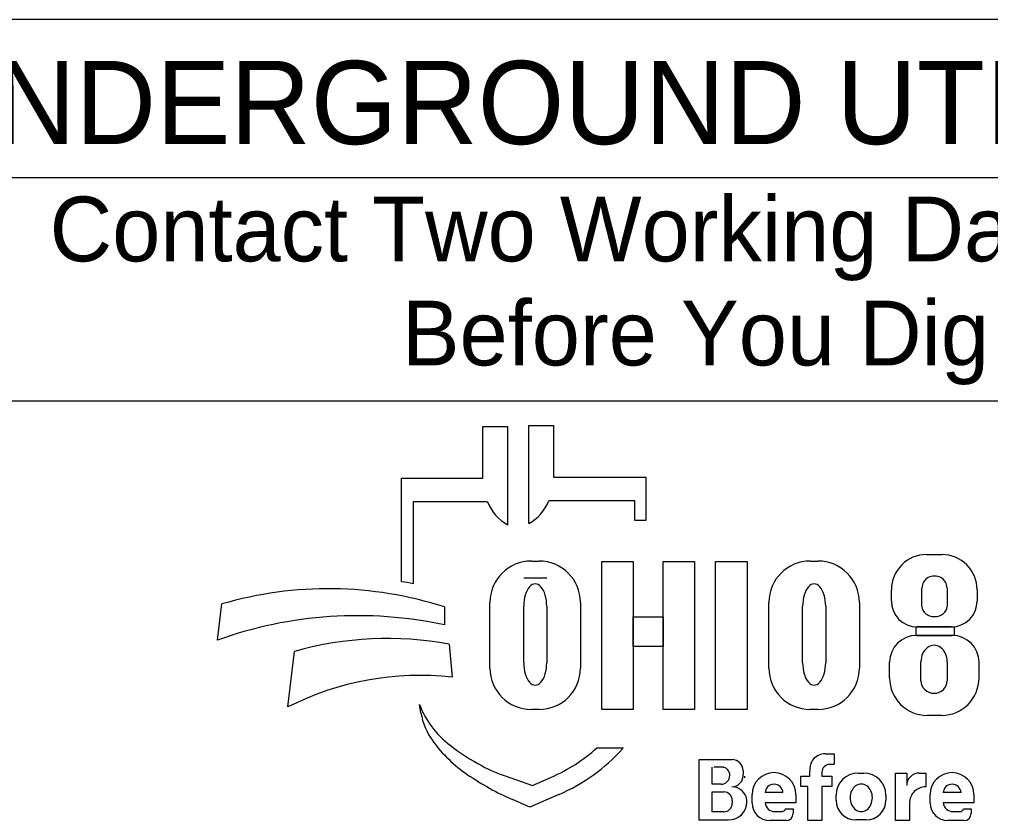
# Model space of a CAD drawing. Extents: x 0 to 43.4, y -8.1 to 22.
# Drawn here: x 13.492 to 15.591, y 1.457 to 3.19 of the extents above; entities that cross this region are included whole.
import ezdxf

# ---------------------------------------------------------------- set-up
doc = ezdxf.new("R2010")
doc.units = 0
doc.layers.add('SH_Data', color=7, linetype='Continuous')
doc.layers.add('SH_Text', color=7, linetype='Continuous')

msp = doc.modelspace()

# ---------------------------------------------------------------- linework, layer by layer
at = {"layer": 'SH_Data'}
for p, q in [((17.3873, 3.1897), (13.1373, 3.1897)), ((13.1373, 2.8481), (17.3873, 2.8481)), ((13.1373, 2.3647), (17.3873, 2.3647))]:
    msp.add_line(p, q, dxfattribs=at)
at = {"layer": 'SH_Text'}
for p, q in [((14.5926, 2.0994), (14.5926, 2.3115)), ((14.5926, 2.3115), (14.6462, 2.3115)), ((14.6462, 2.3115), (14.6462, 2.2)), ((14.4933, 2.1977), (14.4933, 2.3092)), ((14.4933, 2.3092), (14.5469, 2.3092)), ((14.5469, 2.3092), (14.5469, 2.0971)), ((14.3173, 1.9738), (14.3173, 2.1977)), ((14.3173, 2.1977), (14.4933, 2.1977)), ((14.6462, 2.2), (14.8455, 2.2)), ((14.8455, 2.2), (14.8455, 2.1062)), ((14.3426, 2.1462), (14.3426, 1.9694)), ((14.5037, 2.1462), (14.3426, 2.1462)), ((14.8222, 2.1485), (14.6358, 2.1485)), ((14.8222, 2.1062), (14.8222, 2.1485)), ((14.8455, 2.1062), (14.8222, 2.1062)), ((14.5983, 2.0185), (14.6148, 2.0185)), ((15.2013, 2.0185), (15.2178, 2.0185)), ((15.4528, 2.0325), (15.4856, 2.0325)), ((14.6315, 1.9815), (14.5817, 1.9815)), ((15.3765, 1.9319), (15.3765, 1.9562)), ((15.4427, 1.9205), (15.4427, 1.9598)), ((15.4968, 1.9598), (15.4968, 1.9205)), ((15.5619, 1.9562), (15.5619, 1.9319)), ((13.92, 1.8475), (13.9293, 1.9256)), ((14.4106, 1.9191), (14.4106, 1.8803)), ((14.5088, 1.787), (14.5088, 1.929)), ((14.5817, 1.7984), (14.5817, 1.9207)), ((14.6315, 1.9207), (14.6315, 1.7984)), ((14.7043, 1.929), (14.7043, 1.787)), ((15.1118, 1.787), (15.1118, 1.929)), ((15.1847, 1.7984), (15.1847, 1.9207)), ((15.2345, 1.9207), (15.2345, 1.7984)), ((15.3073, 1.929), (15.3073, 1.787)), ((15.5059, 1.8759), (15.4325, 1.8759)), ((15.4307, 1.8576), (15.5081, 1.8576)), ((14.4206, 1.8385), (14.4268, 1.7676)), ((14.0718, 1.7029), (14.0865, 1.8231)), ((15.3728, 1.7657), (15.3728, 1.7997)), ((15.4403, 1.7597), (15.4403, 1.8006)), ((15.4972, 1.8006), (15.4972, 1.7597)), ((15.5659, 1.7997), (15.5659, 1.7657)), ((14.3595, 1.69), (14.3564, 1.708)), ((14.6148, 1.6975), (14.5983, 1.6975)), ((15.2178, 1.6975), (15.2013, 1.6975)), ((15.485, 1.6847), (15.4538, 1.6847)), ((14.7398, 1.6142), (14.7972, 1.6142)), ((15.2336, 1.6019), (15.2531, 1.6019)), ((15.2531, 1.6019), (15.2531, 1.579)), ((14.9611, 1.4584), (14.9611, 1.5891)), ((14.9611, 1.5891), (15.0322, 1.5891)), ((15.2531, 1.5785), (15.243, 1.5785)), ((14.5413, 1.5538), (14.6008, 1.5333)), ((14.989, 1.5357), (14.989, 1.5726)), ((15.0142, 1.5726), (14.993, 1.5726)), ((15.056, 1.5654), (15.056, 1.5575)), ((15.2004, 1.5536), (15.2004, 1.564)), ((15.2265, 1.562), (15.2265, 1.5536)), ((15.3049, 1.5601), (15.317, 1.5601)), ((15.3851, 1.4572), (15.3851, 1.5599)), ((15.3851, 1.5599), (15.4097, 1.5599)), ((15.4097, 1.5599), (15.4097, 1.533)), ((15.4369, 1.5599), (15.4508, 1.5599)), ((15.4508, 1.5599), (15.4508, 1.5303)), ((14.6008, 1.5333), (14.6418, 1.5511)), ((15.0084, 1.5357), (14.989, 1.5357)), ((15.181, 1.5306), (15.181, 1.5536)), ((15.181, 1.5536), (15.2004, 1.5536)), ((15.2265, 1.5536), (15.248, 1.5536)), ((15.248, 1.5536), (15.248, 1.5306)), ((14.658, 1.5137), (14.5947, 1.4863)), ((14.989, 1.4762), (14.989, 1.5191)), ((14.989, 1.5191), (15.0146, 1.5191)), ((15.0756, 1.4952), (15.0756, 1.5136)), ((15.1422, 1.5176), (15.1037, 1.5176)), ((15.1701, 1.5136), (15.1701, 1.4959)), ((15.196, 1.5306), (15.181, 1.5306)), ((15.196, 1.4572), (15.196, 1.5306)), ((15.248, 1.5306), (15.2265, 1.5306)), ((15.2265, 1.5306), (15.2265, 1.4572)), ((15.257, 1.5015), (15.257, 1.5123)), ((15.3648, 1.5123), (15.3648, 1.5015)), ((15.4605, 1.4952), (15.4605, 1.5136)), ((15.5271, 1.5176), (15.4886, 1.5176)), ((15.5551, 1.5136), (15.5551, 1.4959)), ((14.5947, 1.4863), (14.5574, 1.5027)), ((15.0327, 1.501), (15.0327, 1.4946)), ((15.0641, 1.4981), (15.0641, 1.4978)), ((15.1701, 1.4959), (15.1037, 1.4959)), ((15.4156, 1.4953), (15.4156, 1.4572)), ((15.5551, 1.4959), (15.4886, 1.4959)), ((15.0143, 1.4762), (14.989, 1.4762)), ((15.1246, 1.4767), (15.1388, 1.4767)), ((15.1473, 1.4823), (15.1642, 1.4823)), ((15.1642, 1.4823), (15.1642, 1.4724)), ((15.5096, 1.4767), (15.5237, 1.4767)), ((15.5323, 1.4823), (15.5491, 1.4823)), ((15.5491, 1.4823), (15.5491, 1.4724)), ((15.0247, 1.4584), (14.9611, 1.4584)), ((15.149, 1.4572), (15.1136, 1.4572)), ((15.2265, 1.4572), (15.196, 1.4572)), ((15.322, 1.4588), (15.2998, 1.4588)), ((15.4156, 1.4572), (15.3851, 1.4572)), ((15.5339, 1.4572), (15.4985, 1.4572))]:
    msp.add_line(p, q, dxfattribs=at)
for points in [[(14.7507, 2.0174), (14.8187, 2.0174), (14.8187, 1.6975), (14.7507, 1.6975)], [(14.8829, 2.0174), (14.9508, 2.0174), (14.9508, 1.6975), (14.8829, 1.6975)], [(14.9962, 2.0174), (15.0649, 2.0174), (15.0649, 1.6975), (14.9962, 1.6975)], [(14.8187, 1.8976), (14.8829, 1.8976), (14.8829, 1.8336), (14.8187, 1.8336)], [(15.4304, 1.8759), (15.5121, 1.8759), (15.5121, 1.8574), (15.4304, 1.8574)]]:
    msp.add_lwpolyline(points, close=True, dxfattribs=at)
for centre, radius, start, end in [((14.595, 2.183), 0.0985, 201.9296, 240.7469), ((14.5445, 2.1853), 0.0985, 299.2531, 338.0704), ((14.5983, 1.929), 0.0895, 90, 180), ((14.6148, 1.929), 0.0895, 0, 90), ((15.2013, 1.929), 0.0895, 90, 180), ((15.2178, 1.929), 0.0895, 0, 90), ((15.4528, 1.9562), 0.0763, 90, 180), ((15.4856, 1.9562), 0.0763, 0, 90), ((14.1892, 1.1648), 0.8191, 79.2074, 81.0007), ((14.1594, 1.1395), 0.8191, 72.1402, 106.3144), ((15.4325, 1.9319), 0.056, 180, 270), ((15.5059, 1.9319), 0.056, 270, 0), ((14.2225, 1.0084), 0.8919, 77.8238, 109.8274), ((14.2864, 1.1187), 0.7322, 79.44, 105.8467), ((15.4307, 1.7997), 0.0579, 90, 180), ((15.5081, 1.7997), 0.0579, 0, 90), ((14.5983, 1.787), 0.0895, 180, 270), ((14.6148, 1.787), 0.0895, 270, 0), ((15.2013, 1.787), 0.0895, 180, 270), ((15.2178, 1.787), 0.0895, 270, 0), ((14.3584, 1.1355), 0.6357, 83.8248, 116.8021), ((15.4538, 1.7657), 0.081, 180, 270), ((15.485, 1.7657), 0.081, 270, 0), ((14.5438, 1.7801), 0.2008, 201.0457, 232.5314), ((14.5008, 1.7142), 0.1433, 189.6817, 216.0884), ((14.6344, 1.8116), 0.3088, 216.0884, 235.7167), ((14.7364, 2.0313), 0.5173, 232.5314, 241.794), ((14.4984, 1.8816), 0.3602, 293.4582, 312.0712), ((14.4984, 1.8816), 0.401, 293.4582, 317.8286), ((15.2336, 1.5684), 0.0335, 90, 187.5187), ((14.6512, 1.8725), 0.3371, 241.794, 250.9821), ((15.0322, 1.5654), 0.0238, 0, 90), ((15.243, 1.562), 0.0165, 90, 180), ((14.801, 2.0558), 0.6044, 235.7167, 246.2325), ((15.0084, 1.5544), 0.0187, 270, 2.0582), ((15.0103, 1.5557), 0.0169, 357.8325, 90), ((15.0318, 1.5547), 0.0243, 270, 6.6529), ((15.1229, 1.5136), 0.0473, 0, 180), ((15.3049, 1.5123), 0.0478, 90, 180), ((15.317, 1.5123), 0.0478, 0, 90), ((15.4365, 1.533), 0.0269, 89.2449, 180), ((15.5078, 1.5136), 0.0473, 0, 180), ((15.0424, 1.5532), 0.0175, 347.4023, 0), ((15.1229, 1.5166), 0.0193, 2.9632, 177.0368), ((15.5078, 1.5166), 0.0193, 2.9632, 177.0368), ((15.0146, 1.501), 0.0181, 0, 90), ((15.032, 1.4983), 0.0321, 4.0748, 90), ((15.4505, 1.4953), 0.0349, 89.6033, 180), ((15.0143, 1.4946), 0.0184, 270, 0), ((15.0247, 1.4978), 0.0393, 270, 0), ((15.0311, 1.4981), 0.033, 0, 11.7502), ((15.1136, 1.4952), 0.038, 180, 270), ((15.1246, 1.4977), 0.021, 184.827, 270), ((15.2998, 1.5015), 0.0428, 180, 270), ((15.322, 1.5015), 0.0428, 270, 0), ((15.4985, 1.4952), 0.038, 180, 270), ((15.5096, 1.4977), 0.021, 184.827, 270), ((15.1388, 1.4861), 0.00938, 270, 335.9979), ((15.149, 1.4724), 0.0152, 270, 0), ((15.5237, 1.4861), 0.00938, 270, 335.9979), ((15.5339, 1.4724), 0.0152, 270, 0)]:
    msp.add_arc(centre, radius, start, end, dxfattribs=at)
for centre, major_axis, ratio, start_param, end_param in [((15.4698, 1.9598), (0.0271, 0), 0.969373, 0, 3.141593), ((14.6066, 1.9207), (0, 0.0484), 0.514403, 4.712389, 7.853982), ((15.2096, 1.9207), (0, 0.0484), 0.514403, 4.712389, 7.853982), ((15.4698, 1.9205), (0.0271, 0), 0.818453, 3.141593, 6.283185), ((15.4688, 1.8006), (0, 0.0358), 0.794529, 4.712389, 7.853982), ((14.6066, 1.7984), (0, 0.0484), 0.514403, 1.570796, 4.712389), ((15.2096, 1.7984), (0, 0.0484), 0.514403, 1.570796, 4.712389), ((15.4688, 1.7597), (0.0284, 0), 0.959837, 3.141593, 6.283185), ((15.3114, 1.5069), (0, 0.029), 0.832186, 4.712389, 7.853982), ((15.3114, 1.5069), (0, 0.0302), 0.797287, 1.570796, 4.712389)]:
    msp.add_ellipse(centre, major_axis=major_axis, ratio=ratio, start_param=start_param, end_param=end_param, dxfattribs=at)

# ---------------------------------------------------------------- texts
for s, height, p in [('UNDERGROUND UTILITIES', 0.18, (13.2654, 2.92)), ('Contact Two Working Days', 0.14, (13.5569, 2.6665)), ('Before You Dig', 0.14, (14.3181, 2.4415))]:
    msp.add_text(s, height=height, dxfattribs=at).set_placement(p)

doc.saveas('drawing.dxf')
